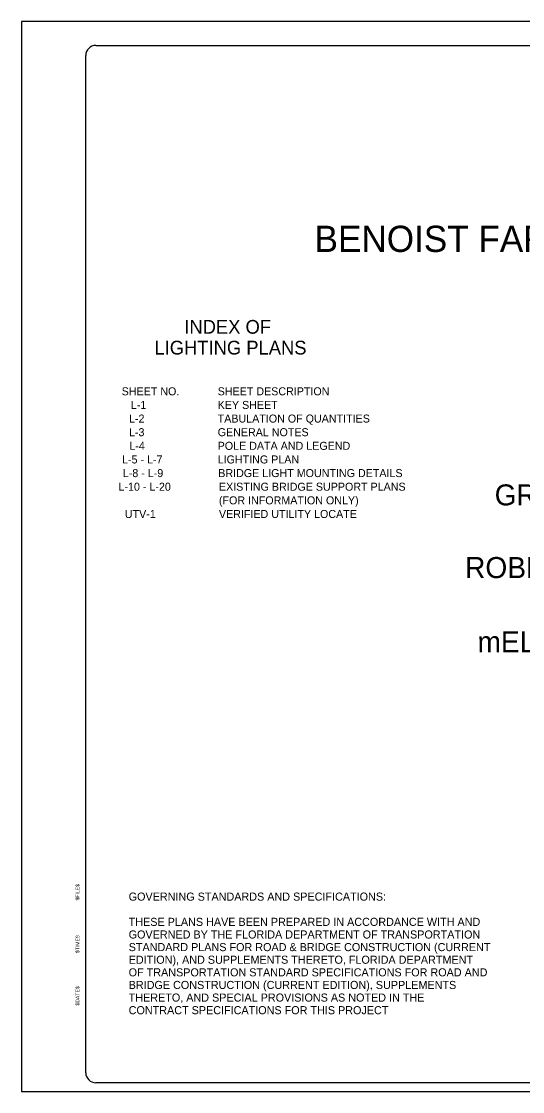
# Model space of a CAD drawing. Extents: x 801329 to 1179195, y 842463 to 1027285.
# Drawn here: x 801329 to 885746, y 842463 to 1022663 of the extents above; entities that cross this region are included whole.
import ezdxf

# ---------------------------------------------------------------- set-up
doc = ezdxf.new("R2010")
doc.units = 0
for name, color, linetype in [('Default', 7, 'Continuous'), ('PlotBorder_dp', 7, 'Continuous'), ('TextLabel', 7, 'Continuous')]:
    doc.layers.add(name, color=color, linetype=linetype)

msp = doc.modelspace()

# ---------------------------------------------------------------- linework, layer by layer
at = {"layer": 'Default'}
for p, q in [((813867, 1018625), (1063315, 1018625)), ((812167, 845650), (812167, 1016925)), ((1063315, 843950), (813867, 843950))]:
    msp.add_line(p, q, dxfattribs=at)
for centre, start, end in [((813867, 1016925), 90, 180), ((813867, 845650), 180, 270)]:
    msp.add_arc(centre, 1700, start, end, dxfattribs=at)
at = {"layer": 'PlotBorder_dp'}
msp.add_lwpolyline([(801329, 842463), (1085229, 842463), (1085229, 1022663), (801329, 1022663)], close=True, dxfattribs=at)

# ---------------------------------------------------------------- texts
at = {"layer": 'Default'}
for s, height, p in [('INDEX OF ', 2312.8, (828768, 970077)), ('LIGHTING PLANS', 2312.85, (823742, 966574)), ('SHEET NO.', 1348.1, (818216, 959704)), ('SHEET DESCRIPTION                  ', 1347.67, (834388, 959704)), ('   L-1   ', 1348.1, (818266, 957409)), ('KEY SHEET                          ', 1347.67, (834388, 957409)), ('   L-2   ', 1348.1, (817954, 955114)), ('TABULATION OF QUANTITIES           ', 1347.67, (834388, 955114)), ('   L-3   ', 1348.1, (817944, 952819)), ('GENERAL NOTES                      ', 1347.67, (834388, 952819)), ('   L-4   ', 1348.1, (818008, 950524)), ('POLE DATA AND LEGEND               ', 1347.67, (834388, 950524)), ('L-5 - L-7', 1348.1, (818275, 948229)), ('LIGHTING PLAN                      ', 1347.67, (834388, 948229)), ('L-8 - L-9', 1348.1, (818409, 945934)), ('BRIDGE LIGHT MOUNTING DETAILS      ', 1347.67, (834487, 945934)), ('L-10 - L-20', 1348.1, (817686, 943639)), ('EXISTING BRIDGE SUPPORT PLANS      ', 1347.67, (834602, 943639)), ('(FOR INFORMATION ONLY)             ', 1347.67, (834602, 941344)), ('   UTV-1   ', 1348.1, (817251, 939049)), ('VERIFIED UTILITY LOCATE            ', 1347.67, (834602, 939049)), ('GOVERNING STANDARDS AND SPECIFICATIONS:', 1360, (819396, 874614)), ('THESE PLANS HAVE BEEN PREPARED IN ACCORDANCE WITH AND', 1360, (819396, 870364)), ('GOVERNED BY THE FLORIDA DEPARTMENT OF TRANSPORTATION', 1360, (819396, 868239)), ('STANDARD PLANS FOR ROAD & BRIDGE CONSTRUCTION (CURRENT', 1360, (819396, 866114)), ('EDITION), AND SUPPLEMENTS THERETO, FLORIDA DEPARTMENT ', 1360, (819396, 863989)), ('OF TRANSPORTATION STANDARD SPECIFICATIONS FOR ROAD AND ', 1360, (819396, 861864)), ('BRIDGE CONSTRUCTION (CURRENT EDITION), SUPPLEMENTS ', 1360, (819396, 859739)), ('THERETO, AND SPECIAL PROVISIONS AS NOTED IN THE ', 1360, (819396, 857614)), ('CONTRACT SPECIFICATIONS FOR THIS PROJECT', 1360, (819396, 855489))]:
    msp.add_text(s, height=height, dxfattribs=at).set_placement(p)
for s, p in [('$FILE$', (811084, 874655)), ('$TIME$', (811091, 865787)), ('$DATE$', (811082, 856952))]:
    msp.add_text(s, height=619.5, rotation=90, dxfattribs=at).set_placement(p)
at = {"layer": 'TextLabel'}
msp.add_text('BENOIST FARMS ROAD - SR 80 (SOUTHERN BOULEVARD) TO BELVEDERE ROAD', height=4419.99, dxfattribs=at).set_placement((850713, 983842))
for s, height, p in [('GREGG K. WEISS', 3531.23, (881043, 941169)), ('ROBERT S. WEINROTH', 3544.29, (876054, 928929)), ('mELISSA mCkINLAY', 3531.23, (878159, 916417))]:
    msp.add_text(s, height=height, rotation=360, dxfattribs=at).set_placement(p)

doc.saveas('drawing.dxf')
